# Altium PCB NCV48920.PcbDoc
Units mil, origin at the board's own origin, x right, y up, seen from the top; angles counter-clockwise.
Board outline 1000 x 1000 mil, 4 copper layers (Top Layer, GND_int, PWR_int, Bottom Layer), stack 61.654 mil thick; 6 components, 8 nets, 61 pads, 244 vias.
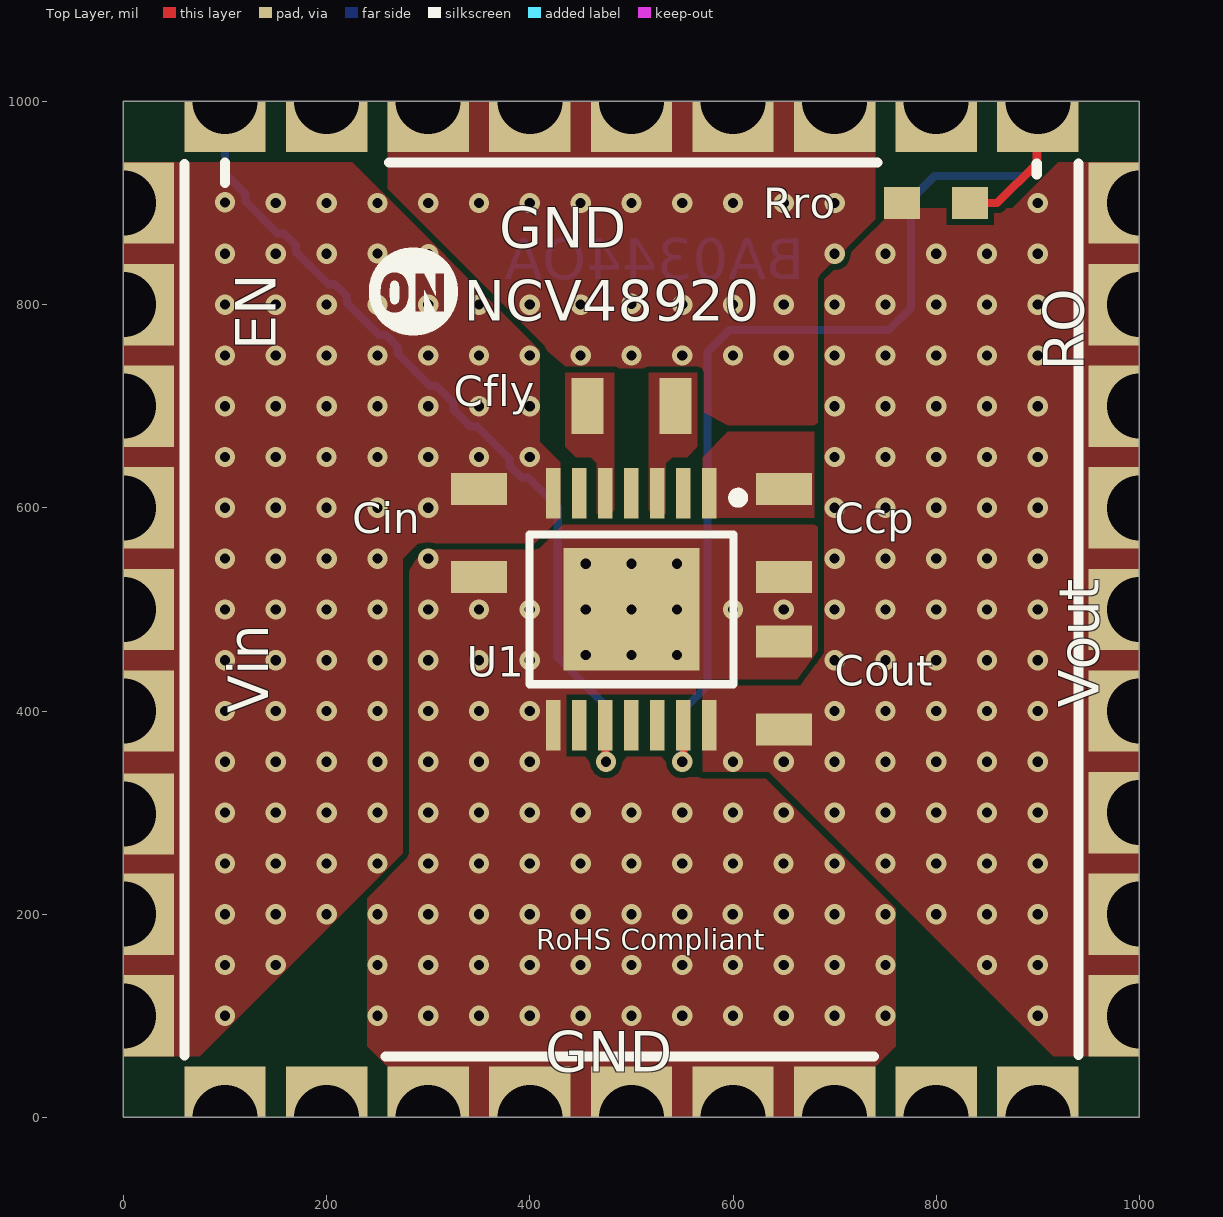
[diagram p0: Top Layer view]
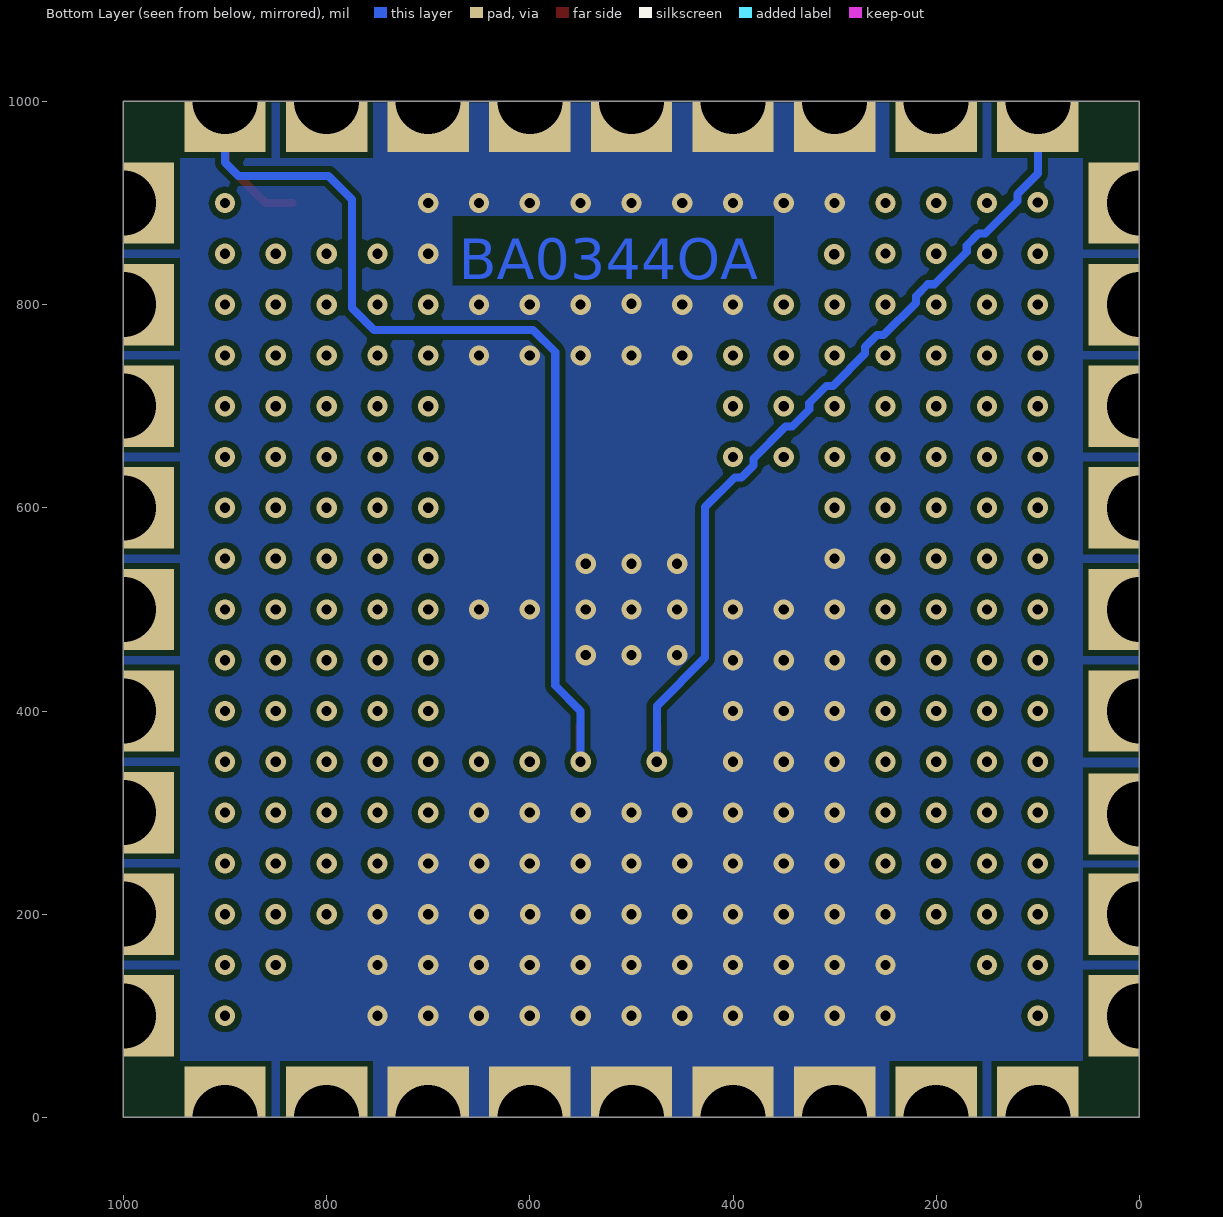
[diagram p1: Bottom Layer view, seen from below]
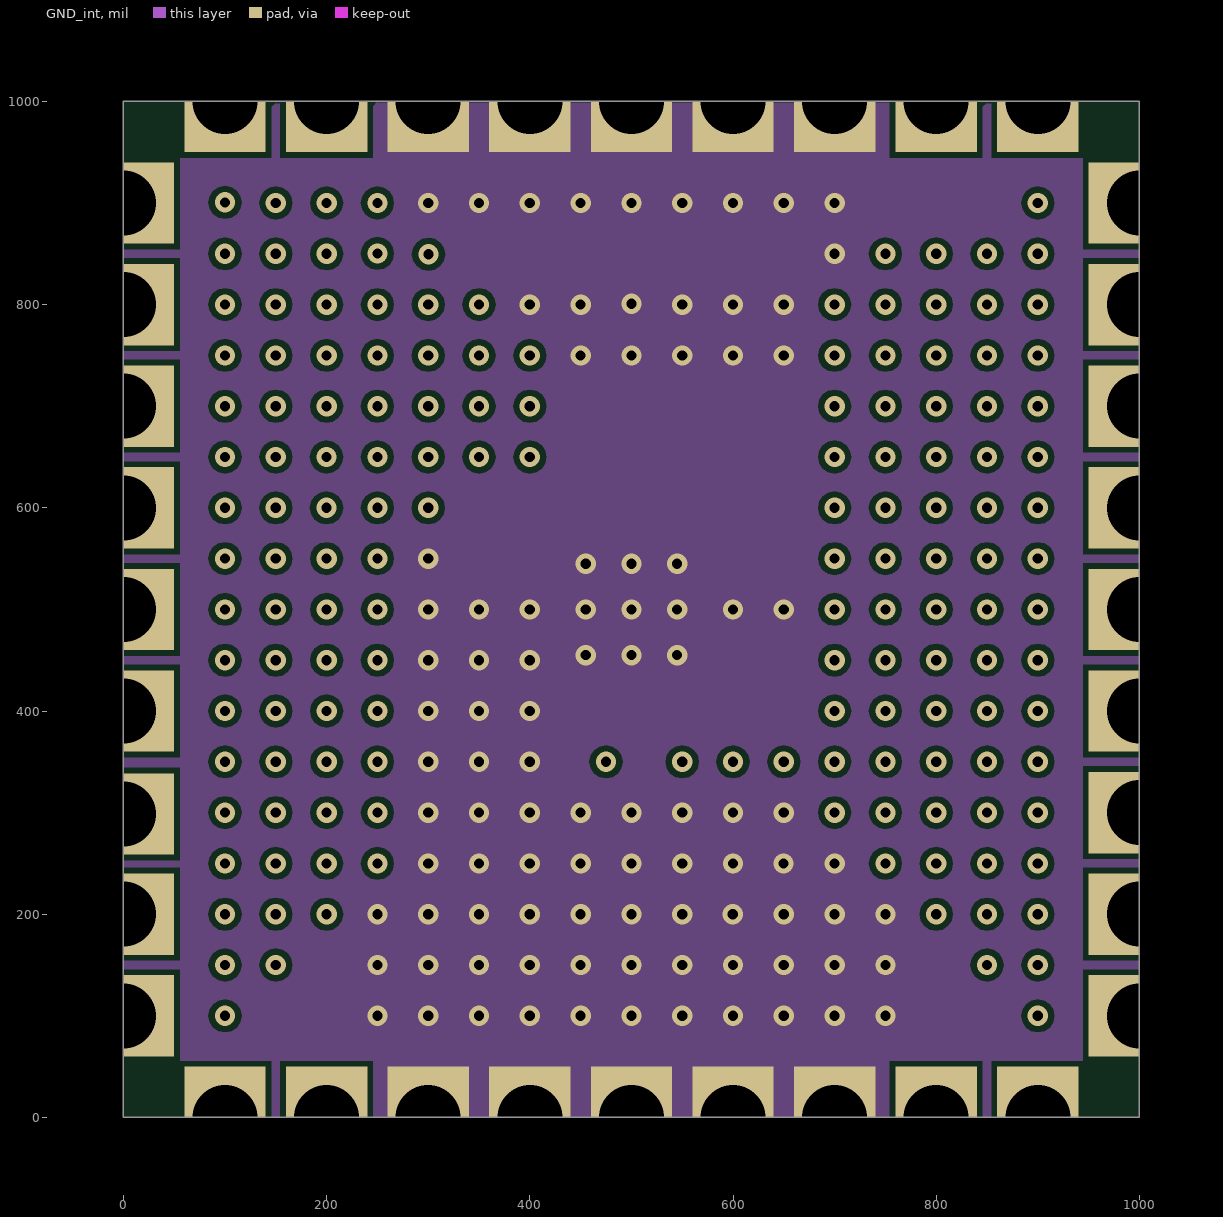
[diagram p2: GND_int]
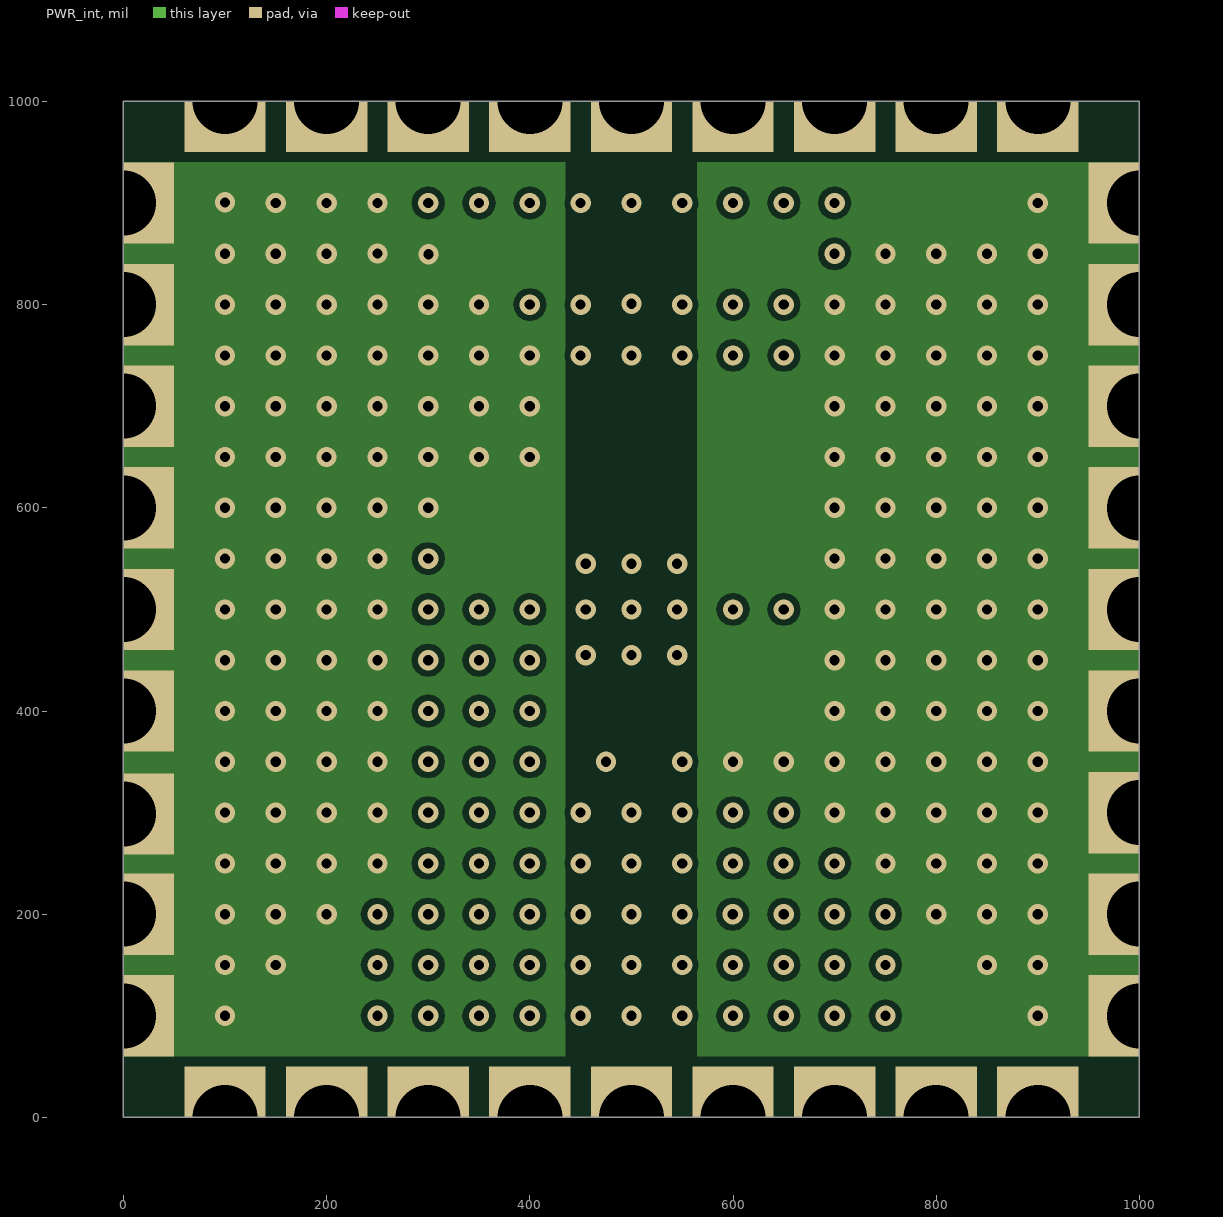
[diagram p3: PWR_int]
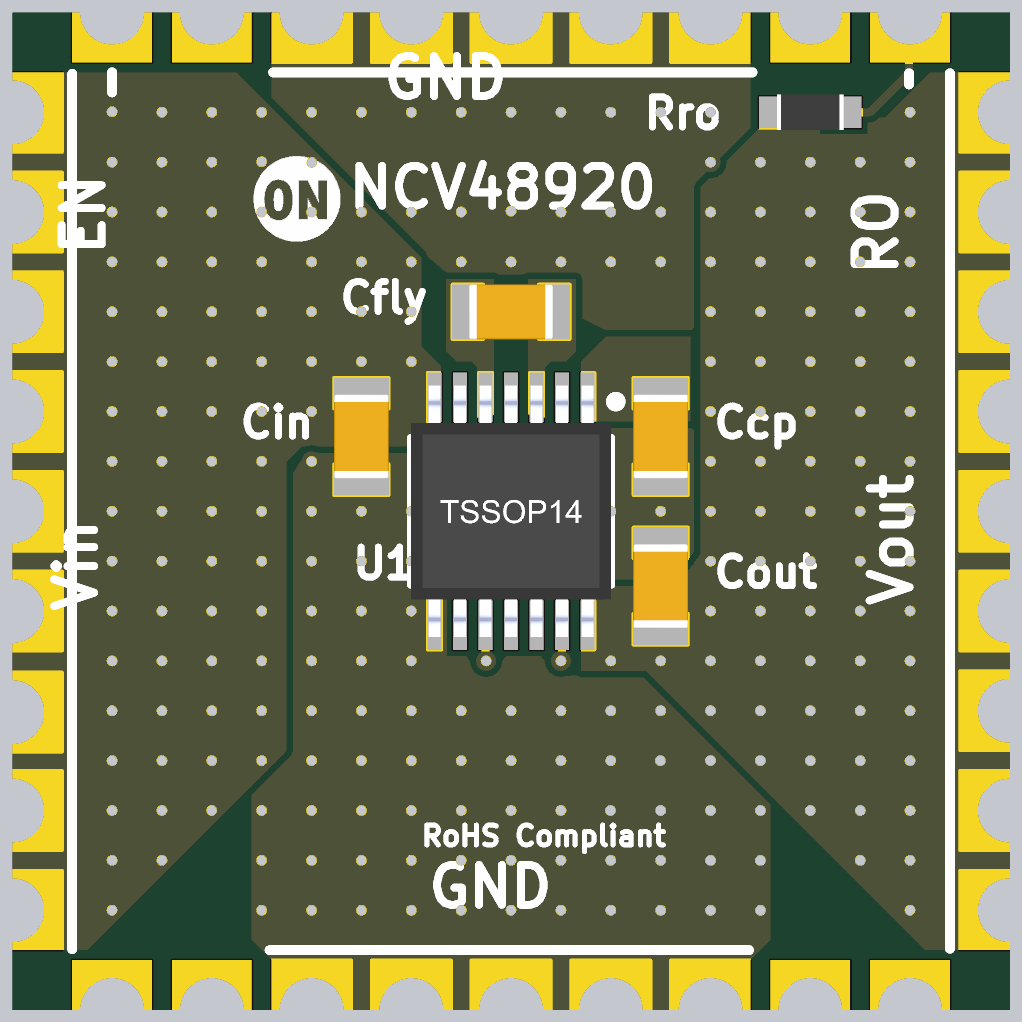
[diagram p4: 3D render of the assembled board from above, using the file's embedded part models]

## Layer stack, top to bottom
Top Solder: solder mask 0.4, Solder Resist, Dk 3.5
Top Layer: signal copper 0.7087
Dielectric 1: core 14.7638, FR-4, Dk 4.2
GND_int: signal copper 1.378
Dielectric 3: prepreg 27.9528, Dk 4.2
PWR_int: signal copper 1.378
Dielectric 2: core 14.7638, Dk 4.2
Bottom Layer: signal copper 0.7087
Bottom Solder: solder mask 0.4, Solder Resist, Dk 3.5

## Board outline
0,0 1000,0 1000,1000 0,1000
cut-out: -150,-400
cut-out: 0,-300

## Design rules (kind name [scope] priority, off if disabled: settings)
Clearance [All] p1: gap=6 ignorepadtopadclearanceinfootprint=FALSE except(0: Arc-Hole Track-Hole SMDPad-Hole THPad-Hole Via-Hole Fill-Hole Poly-Hole Region-Hole Text-Hole)
ComponentClearance [All] p1: gap=0 collisioncheckmode=3 verticalgap=0 showdistances=FALSE
DiffPairsRouting [All] p1: maxlimit=10 minlimit=6 mostfreqgap=10 toplayer_minwidth=6 toplayer_maxwidth=20 toplayer_prefwidth=10 midlayer1_minwidth=6 midlayer1_maxwidth=20 midlayer1_prefwidth=10 midlayer2_minwidth=6 midlayer2_maxwidth=20 midlayer2_prefwidth=10 bottomlayer_minwidth=6 bottomlayer_maxwidth=20 bottomlayer_prefwidth=10 maxuncoupledlength=500
Height [All] p1: minheight=0 maxheight=3000 prefheight=500
HoleSize [All] p1: absolutevalues=TRUE maxlimit=400 minlimit=8 maxpercent=80.000 minpercent=20.000
MinimumSolderMaskSliver [All] p1: minsoldermaskwidth=1.57
PlaneClearance [All] p1: clearance=6
PolygonConnect Polygon_Direct [All] p1: connectstyle=Direct reliefconductorwidth=10 reliefentries=4 polygonreliefangle="90 Angle" airgapwidth=10
PolygonConnect PolygonConnect_85 [All vs IsNamedPolygon('GND_L01_P2321')] p2: connectstyle=Direct reliefconductorwidth=10 reliefentries=4 polygonreliefangle="90 Angle" airgapwidth=10
PolygonConnect PolygonConnect_84 [All vs IsNamedPolygon('GND_L03_P1821')] p3: connectstyle=Direct reliefconductorwidth=10 reliefentries=4 polygonreliefangle="90 Angle" airgapwidth=10
PolygonConnect PolygonConnect_83 [All vs IsNamedPolygon('VOUTMP_L05_P1813')] p4: connectstyle=Direct reliefconductorwidth=10 reliefentries=4 polygonreliefangle="90 Angle" airgapwidth=10
PolygonConnect PolygonConnect_82 [All vs IsNamedPolygon('VOUTMP_L04_P1815')] p5: connectstyle=Direct reliefconductorwidth=10 reliefentries=4 polygonreliefangle="90 Angle" airgapwidth=10
PolygonConnect PolygonConnect_81 [All vs IsNamedPolygon('GND_L06_P2169')] p6: connectstyle=Direct reliefconductorwidth=10 reliefentries=4 polygonreliefangle="90 Angle" airgapwidth=10
PolygonConnect PolygonConnect_80 [All vs IsNamedPolygon('GND_L06_P2377')] p7: connectstyle=Direct reliefconductorwidth=10 reliefentries=4 polygonreliefangle="90 Angle" airgapwidth=10
PolygonConnect PolygonConnect_79 [All vs IsNamedPolygon('VOUTMP_L04_P1803')] p8: connectstyle=Direct reliefconductorwidth=10 reliefentries=4 polygonreliefangle="90 Angle" airgapwidth=10
PolygonConnect PolygonConnect_78 [All vs IsNamedPolygon('VCC_DUT_L04_P1801')] p9: connectstyle=Direct reliefconductorwidth=10 reliefentries=4 polygonreliefangle="90 Angle" airgapwidth=10
PolygonConnect PolygonConnect_77 [All vs IsNamedPolygon('GND_L06_P1795')] p10: thpad.connectstyle=Relief thpad.reliefconductorwidth=10 thpad.reliefentries=4 thpad.polygonreliefangle="90 Angle" thpad.airgapwidth=10 smdpad.connectstyle=Direct smdpad.reliefconductorwidth=10 smdpad.reliefentries=4 smdpad.polygonreliefangle="90 Angle" smdpad.airgapwidth=10 via.connectstyle=Direct via.reliefconductorwidth=10 via.reliefentries=4 via.polygonreliefangle="90 Angle" via.airgapwidth=10
PolygonConnect PolygonConnect_76 [All vs IsNamedPolygon('GND_L02_P1793')] p11: connectstyle=Direct reliefconductorwidth=10 reliefentries=4 polygonreliefangle="90 Angle" airgapwidth=10
PolygonConnect PolygonConnect_75 [All vs IsNamedPolygon('GND_L03_P1791')] p12: thpad.connectstyle=Relief thpad.reliefconductorwidth=10 thpad.reliefentries=4 thpad.polygonreliefangle="90 Angle" thpad.airgapwidth=10 smdpad.connectstyle=Direct smdpad.reliefconductorwidth=10 smdpad.reliefentries=4 smdpad.polygonreliefangle="90 Angle" smdpad.airgapwidth=10 via.connectstyle=Direct via.reliefconductorwidth=10 via.reliefentries=4 via.polygonreliefangle="90 Angle" via.airgapwidth=10
PolygonConnect PolygonConnect_74 [All vs IsNamedPolygon('NETQLMPB_5_L06_P1787')] p13: thpad.connectstyle=Relief thpad.reliefconductorwidth=10 thpad.reliefentries=4 thpad.polygonreliefangle="90 Angle" thpad.airgapwidth=10 smdpad.connectstyle=Direct smdpad.reliefconductorwidth=10 smdpad.reliefentries=4 smdpad.polygonreliefangle="90 Angle" smdpad.airgapwidth=10 via.connectstyle=Direct via.reliefconductorwidth=10 via.reliefentries=4 via.polygonreliefangle="90 Angle" via.airgapwidth=10
PolygonConnect PolygonConnect_73 [All vs IsNamedPolygon('NETQLMPA_5_L06_P1789')] p14: thpad.connectstyle=Relief thpad.reliefconductorwidth=10 thpad.reliefentries=4 thpad.polygonreliefangle="90 Angle" thpad.airgapwidth=10 smdpad.connectstyle=Direct smdpad.reliefconductorwidth=10 smdpad.reliefentries=4 smdpad.polygonreliefangle="90 Angle" smdpad.airgapwidth=10 via.connectstyle=Direct via.reliefconductorwidth=10 via.reliefentries=4 via.polygonreliefangle="90 Angle" via.airgapwidth=10
PolygonConnect PolygonConnect_72 [All vs IsNamedPolygon('NETQLMPC_5_L06_P1738')] p15: thpad.connectstyle=Relief thpad.reliefconductorwidth=10 thpad.reliefentries=4 thpad.polygonreliefangle="90 Angle" thpad.airgapwidth=10 smdpad.connectstyle=Direct smdpad.reliefconductorwidth=10 smdpad.reliefentries=4 smdpad.polygonreliefangle="90 Angle" smdpad.airgapwidth=10 via.connectstyle=Direct via.reliefconductorwidth=10 via.reliefentries=4 via.polygonreliefangle="90 Angle" via.airgapwidth=10
PolygonConnect PolygonConnect_71 [All vs IsNamedPolygon('NETQL12_5_L06_P1740')] p16: thpad.connectstyle=Relief thpad.reliefconductorwidth=10 thpad.reliefentries=4 thpad.polygonreliefangle="90 Angle" thpad.airgapwidth=10 smdpad.connectstyle=Direct smdpad.reliefconductorwidth=10 smdpad.reliefentries=4 smdpad.polygonreliefangle="90 Angle" smdpad.airgapwidth=10 via.connectstyle=Direct via.reliefconductorwidth=10 via.reliefentries=4 via.polygonreliefangle="90 Angle" via.airgapwidth=10
PolygonConnect PolygonConnect_70 [All vs IsNamedPolygon('NETQL12_5_L06_P1740')] p17: thpad.connectstyle=Relief thpad.reliefconductorwidth=10 thpad.reliefentries=4 thpad.polygonreliefangle="90 Angle" thpad.airgapwidth=10 smdpad.connectstyle=Direct smdpad.reliefconductorwidth=10 smdpad.reliefentries=4 smdpad.polygonreliefangle="90 Angle" smdpad.airgapwidth=10 via.connectstyle=Direct via.reliefconductorwidth=10 via.reliefentries=4 via.polygonreliefangle="90 Angle" via.airgapwidth=10
PolygonConnect PolygonConnect_69 [All vs IsNamedPolygon('NETQLMPD_5_L06_P1736')] p18: thpad.connectstyle=Relief thpad.reliefconductorwidth=10 thpad.reliefentries=4 thpad.polygonreliefangle="90 Angle" thpad.airgapwidth=10 smdpad.connectstyle=Direct smdpad.reliefconductorwidth=10 smdpad.reliefentries=4 smdpad.polygonreliefangle="90 Angle" smdpad.airgapwidth=10 via.connectstyle=Direct via.reliefconductorwidth=10 via.reliefentries=4 via.polygonreliefangle="90 Angle" via.airgapwidth=10
PolygonConnect PolygonConnect_68 [All vs IsNamedPolygon('NETQLMPA_5_L06_P1722')] p19: thpad.connectstyle=Relief thpad.reliefconductorwidth=10 thpad.reliefentries=4 thpad.polygonreliefangle="90 Angle" thpad.airgapwidth=10 smdpad.connectstyle=Direct smdpad.reliefconductorwidth=10 smdpad.reliefentries=4 smdpad.polygonreliefangle="90 Angle" smdpad.airgapwidth=10 via.connectstyle=Direct via.reliefconductorwidth=10 via.reliefentries=4 via.polygonreliefangle="90 Angle" via.airgapwidth=10
PolygonConnect PolygonConnect_67 [All vs IsNamedPolygon('GND_L03_P1716')] p20: connectstyle=Direct reliefconductorwidth=10 reliefentries=4 polygonreliefangle="90 Angle" airgapwidth=10
PolygonConnect PolygonConnect_66 [All vs IsNamedPolygon('GND_L03_P1716')] p21: thpad.connectstyle=Relief thpad.reliefconductorwidth=10 thpad.reliefentries=4 thpad.polygonreliefangle="90 Angle" thpad.airgapwidth=10 smdpad.connectstyle=Relief smdpad.reliefconductorwidth=10 smdpad.reliefentries=4 smdpad.polygonreliefangle="90 Angle" smdpad.airgapwidth=10 via.connectstyle=Direct via.reliefconductorwidth=10 via.reliefentries=4 via.polygonreliefangle="90 Angle" via.airgapwidth=10
PolygonConnect PolygonConnect_65 [All vs IsNamedPolygon('GND_L03_P1716')] p22: thpad.connectstyle=Direct thpad.reliefconductorwidth=10 thpad.reliefentries=4 thpad.polygonreliefangle="90 Angle" thpad.airgapwidth=10 smdpad.connectstyle=Relief smdpad.reliefconductorwidth=10 smdpad.reliefentries=4 smdpad.polygonreliefangle="90 Angle" smdpad.airgapwidth=10 via.connectstyle=Relief via.reliefconductorwidth=10 via.reliefentries=4 via.polygonreliefangle="90 Angle" via.airgapwidth=10
PolygonConnect PolygonConnect_64 [All vs IsNamedPolygon('GND_L03_P1716')] p23: connectstyle=Relief reliefconductorwidth=10 reliefentries=4 polygonreliefangle="90 Angle" airgapwidth=10
PolygonConnect PolygonConnect_63 [All vs IsNamedPolygon('GND_L04_P1728')] p24: connectstyle=Direct reliefconductorwidth=10 reliefentries=4 polygonreliefangle="90 Angle" airgapwidth=10
PolygonConnect PolygonConnect_62 [All vs IsNamedPolygon('G11_L04_P1730')] p25: thpad.connectstyle=Relief thpad.reliefconductorwidth=10 thpad.reliefentries=4 thpad.polygonreliefangle="90 Angle" thpad.airgapwidth=10 smdpad.connectstyle=Direct smdpad.reliefconductorwidth=10 smdpad.reliefentries=4 smdpad.polygonreliefangle="90 Angle" smdpad.airgapwidth=10 via.connectstyle=Direct via.reliefconductorwidth=10 via.reliefentries=4 via.polygonreliefangle="90 Angle" via.airgapwidth=10
PolygonConnect PolygonConnect_61 [All vs IsNamedPolygon('NETQL11_5_L04_P1732')] p26: thpad.connectstyle=Relief thpad.reliefconductorwidth=10 thpad.reliefentries=4 thpad.polygonreliefangle="90 Angle" thpad.airgapwidth=10 smdpad.connectstyle=Direct smdpad.reliefconductorwidth=10 smdpad.reliefentries=4 smdpad.polygonreliefangle="90 Angle" smdpad.airgapwidth=10 via.connectstyle=Direct via.reliefconductorwidth=10 via.reliefentries=4 via.polygonreliefangle="90 Angle" via.airgapwidth=10
PolygonConnect PolygonConnect_60 [All vs IsNamedPolygon('GND_L04_P1718')] p27: connectstyle=Direct reliefconductorwidth=10 reliefentries=4 polygonreliefangle="90 Angle" airgapwidth=10
PolygonConnect PolygonConnect_59 [All vs IsNamedPolygon('G12_L04_P1716')] p28: thpad.connectstyle=Relief thpad.reliefconductorwidth=10 thpad.reliefentries=4 thpad.polygonreliefangle="90 Angle" thpad.airgapwidth=10 smdpad.connectstyle=Direct smdpad.reliefconductorwidth=10 smdpad.reliefentries=4 smdpad.polygonreliefangle="90 Angle" smdpad.airgapwidth=10 via.connectstyle=Direct via.reliefconductorwidth=10 via.reliefentries=4 via.polygonreliefangle="90 Angle" via.airgapwidth=10
PolygonConnect PolygonConnect_58 [All vs IsNamedPolygon('NETQL12_5_L04_P1712')] p29: connectstyle=Direct reliefconductorwidth=10 reliefentries=4 polygonreliefangle="90 Angle" airgapwidth=10
PolygonConnect PolygonConnect_57 [All vs IsNamedPolygon('VOUT111_L01_P1710')] p30: thpad.connectstyle=Direct thpad.reliefconductorwidth=10 thpad.reliefentries=4 thpad.polygonreliefangle="90 Angle" thpad.airgapwidth=10 smdpad.connectstyle=Relief smdpad.reliefconductorwidth=10 smdpad.reliefentries=4 smdpad.polygonreliefangle="90 Angle" smdpad.airgapwidth=10 via.connectstyle=Direct via.reliefconductorwidth=10 via.reliefentries=4 via.polygonreliefangle="90 Angle" via.airgapwidth=10
PolygonConnect PolygonConnect_56 [All vs IsNamedPolygon('VCC_DUT_L06_P1734')] p31: connectstyle=Direct reliefconductorwidth=10 reliefentries=4 polygonreliefangle="90 Angle" airgapwidth=10
PolygonConnect PolygonConnect_55 [All vs IsNamedPolygon('NETC5_1_L01_P1688')] p32: thpad.connectstyle=Relief thpad.reliefconductorwidth=10 thpad.reliefentries=4 thpad.polygonreliefangle="90 Angle" thpad.airgapwidth=10 smdpad.connectstyle=Direct smdpad.reliefconductorwidth=10 smdpad.reliefentries=4 smdpad.polygonreliefangle="90 Angle" smdpad.airgapwidth=10 via.connectstyle=Direct via.reliefconductorwidth=10 via.reliefentries=4 via.polygonreliefangle="90 Angle" via.airgapwidth=10
PolygonConnect PolygonConnect_54 [All vs IsNamedPolygon('GND_L01_P1700')] p33: thpad.connectstyle=Relief thpad.reliefconductorwidth=10 thpad.reliefentries=4 thpad.polygonreliefangle="90 Angle" thpad.airgapwidth=10 smdpad.connectstyle=Direct smdpad.reliefconductorwidth=10 smdpad.reliefentries=4 smdpad.polygonreliefangle="90 Angle" smdpad.airgapwidth=10 via.connectstyle=Direct via.reliefconductorwidth=10 via.reliefentries=4 via.polygonreliefangle="90 Angle" via.airgapwidth=10
PolygonConnect PolygonConnect_53 [All vs IsNamedPolygon('GND_L01_P1608')] p34: thpad.connectstyle=Relief thpad.reliefconductorwidth=10 thpad.reliefentries=4 thpad.polygonreliefangle="90 Angle" thpad.airgapwidth=10 smdpad.connectstyle=Direct smdpad.reliefconductorwidth=10 smdpad.reliefentries=4 smdpad.polygonreliefangle="90 Angle" smdpad.airgapwidth=10 via.connectstyle=Direct via.reliefconductorwidth=10 via.reliefentries=4 via.polygonreliefangle="90 Angle" via.airgapwidth=10
PolygonConnect PolygonConnect_52 [All vs IsNamedPolygon('VREF_L01_P1696')] p35: connectstyle=Direct reliefconductorwidth=10 reliefentries=4 polygonreliefangle="90 Angle" airgapwidth=10
PolygonConnect PolygonConnect_51 [All vs IsNamedPolygon('VREF_L01_P1696')] p36: thpad.connectstyle=Relief thpad.reliefconductorwidth=10 thpad.reliefentries=4 thpad.polygonreliefangle="90 Angle" thpad.airgapwidth=10 smdpad.connectstyle=Direct smdpad.reliefconductorwidth=10 smdpad.reliefentries=4 smdpad.polygonreliefangle="90 Angle" smdpad.airgapwidth=10 via.connectstyle=Direct via.reliefconductorwidth=10 via.reliefentries=4 via.polygonreliefangle="90 Angle" via.airgapwidth=10
PolygonConnect PolygonConnect_50 [All vs IsNamedPolygon('NETC2_1_L01_P1698')] p37: thpad.connectstyle=Relief thpad.reliefconductorwidth=10 thpad.reliefentries=4 thpad.polygonreliefangle="90 Angle" thpad.airgapwidth=10 smdpad.connectstyle=Direct smdpad.reliefconductorwidth=10 smdpad.reliefentries=4 smdpad.polygonreliefangle="90 Angle" smdpad.airgapwidth=10 via.connectstyle=Direct via.reliefconductorwidth=10 via.reliefentries=4 via.polygonreliefangle="90 Angle" via.airgapwidth=10
PolygonConnect PolygonConnect_49 [All vs IsNamedPolygon('NETC1_1_L01_P1694')] p38: thpad.connectstyle=Relief thpad.reliefconductorwidth=10 thpad.reliefentries=4 thpad.polygonreliefangle="90 Angle" thpad.airgapwidth=10 smdpad.connectstyle=Direct smdpad.reliefconductorwidth=10 smdpad.reliefentries=4 smdpad.polygonreliefangle="90 Angle" smdpad.airgapwidth=10 via.connectstyle=Direct via.reliefconductorwidth=10 via.reliefentries=4 via.polygonreliefangle="90 Angle" via.airgapwidth=10
PolygonConnect PolygonConnect_48 [All vs IsNamedPolygon('VID_BUFF_L01_P1690')] p39: thpad.connectstyle=Relief thpad.reliefconductorwidth=10 thpad.reliefentries=4 thpad.polygonreliefangle="90 Angle" thpad.airgapwidth=10 smdpad.connectstyle=Direct smdpad.reliefconductorwidth=10 smdpad.reliefentries=4 smdpad.polygonreliefangle="90 Angle" smdpad.airgapwidth=10 via.connectstyle=Direct via.reliefconductorwidth=10 via.reliefentries=4 via.polygonreliefangle="90 Angle" via.airgapwidth=10
PolygonConnect PolygonConnect_47 [All vs IsNamedPolygon('NETCVCC_1_L01_P1690')] p40: thpad.connectstyle=Relief thpad.reliefconductorwidth=10 thpad.reliefentries=4 thpad.polygonreliefangle="90 Angle" thpad.airgapwidth=10 smdpad.connectstyle=Direct smdpad.reliefconductorwidth=10 smdpad.reliefentries=4 smdpad.polygonreliefangle="90 Angle" smdpad.airgapwidth=10 via.connectstyle=Direct via.reliefconductorwidth=10 via.reliefentries=4 via.polygonreliefangle="90 Angle" via.airgapwidth=10
PolygonConnect PolygonConnect_46 [All vs IsNamedPolygon('REFIN_L01_P1686')] p41: thpad.connectstyle=Relief thpad.reliefconductorwidth=10 thpad.reliefentries=4 thpad.polygonreliefangle="90 Angle" thpad.airgapwidth=10 smdpad.connectstyle=Direct smdpad.reliefconductorwidth=10 smdpad.reliefentries=4 smdpad.polygonreliefangle="90 Angle" smdpad.airgapwidth=10 via.connectstyle=Direct via.reliefconductorwidth=10 via.reliefentries=4 via.polygonreliefangle="90 Angle" via.airgapwidth=10
PolygonConnect PolygonConnect_45 [All vs IsNamedPolygon('CSREF_L06_P1706')] p42: thpad.connectstyle=Relief thpad.reliefconductorwidth=10 thpad.reliefentries=4 thpad.polygonreliefangle="90 Angle" thpad.airgapwidth=10 smdpad.connectstyle=Direct smdpad.reliefconductorwidth=10 smdpad.reliefentries=4 smdpad.polygonreliefangle="90 Angle" smdpad.airgapwidth=10 via.connectstyle=Direct via.reliefconductorwidth=10 via.reliefentries=4 via.polygonreliefangle="90 Angle" via.airgapwidth=10
PolygonConnect PolygonConnect_44 [All vs IsNamedPolygon('GND_L01_P1612')] p43: thpad.connectstyle=Relief thpad.reliefconductorwidth=10 thpad.reliefentries=4 thpad.polygonreliefangle="90 Angle" thpad.airgapwidth=10 smdpad.connectstyle=Direct smdpad.reliefconductorwidth=10 smdpad.reliefentries=4 smdpad.polygonreliefangle="90 Angle" smdpad.airgapwidth=10 via.connectstyle=Direct via.reliefconductorwidth=10 via.reliefentries=4 via.polygonreliefangle="90 Angle" via.airgapwidth=10
PolygonConnect PolygonConnect_43 [All vs IsNamedPolygon('CSREF_L01_P1682')] p44: thpad.connectstyle=Relief thpad.reliefconductorwidth=10 thpad.reliefentries=4 thpad.polygonreliefangle="90 Angle" thpad.airgapwidth=10 smdpad.connectstyle=Direct smdpad.reliefconductorwidth=10 smdpad.reliefentries=4 smdpad.polygonreliefangle="90 Angle" smdpad.airgapwidth=10 via.connectstyle=Direct via.reliefconductorwidth=10 via.reliefentries=4 via.polygonreliefangle="90 Angle" via.airgapwidth=10
PolygonConnect PolygonConnect_42 [All vs IsNamedPolygon('VIN1_L06_P222')] p45: thpad.connectstyle=Relief thpad.reliefconductorwidth=10 thpad.reliefentries=4 thpad.polygonreliefangle="90 Angle" thpad.airgapwidth=10 smdpad.connectstyle=Direct smdpad.reliefconductorwidth=10 smdpad.reliefentries=4 smdpad.polygonreliefangle="90 Angle" smdpad.airgapwidth=10 via.connectstyle=Direct via.reliefconductorwidth=10 via.reliefentries=4 via.polygonreliefangle="90 Angle" via.airgapwidth=10
PolygonConnect PolygonConnect_41 [All vs IsNamedPolygon('VIN1_L06_P1450')] p46: thpad.connectstyle=Relief thpad.reliefconductorwidth=10 thpad.reliefentries=4 thpad.polygonreliefangle="90 Angle" thpad.airgapwidth=10 smdpad.connectstyle=Direct smdpad.reliefconductorwidth=10 smdpad.reliefentries=4 smdpad.polygonreliefangle="90 Angle" smdpad.airgapwidth=10 via.connectstyle=Direct via.reliefconductorwidth=10 via.reliefentries=4 via.polygonreliefangle="90 Angle" via.airgapwidth=10
PolygonConnect PolygonConnect_40 [All vs IsNamedPolygon('VIN1_L06_P1450')] p47: thpad.connectstyle=Relief thpad.reliefconductorwidth=10 thpad.reliefentries=4 thpad.polygonreliefangle="90 Angle" thpad.airgapwidth=10 smdpad.connectstyle=Direct smdpad.reliefconductorwidth=10 smdpad.reliefentries=4 smdpad.polygonreliefangle="90 Angle" smdpad.airgapwidth=10 via.connectstyle=Direct via.reliefconductorwidth=10 via.reliefentries=4 via.polygonreliefangle="90 Angle" via.airgapwidth=10
PolygonConnect PolygonConnect_39 [All vs IsNamedPolygon('VIN1_L06_P1530')] p48: thpad.connectstyle=Relief thpad.reliefconductorwidth=10 thpad.reliefentries=4 thpad.polygonreliefangle="90 Angle" thpad.airgapwidth=10 smdpad.connectstyle=Direct smdpad.reliefconductorwidth=10 smdpad.reliefentries=4 smdpad.polygonreliefangle="90 Angle" smdpad.airgapwidth=10 via.connectstyle=Direct via.reliefconductorwidth=10 via.reliefentries=4 via.polygonreliefangle="90 Angle" via.airgapwidth=10
PolygonConnect PolygonConnect_38 [All vs IsNamedPolygon('VIN1_L06_P1562')] p49: thpad.connectstyle=Relief thpad.reliefconductorwidth=10 thpad.reliefentries=4 thpad.polygonreliefangle="90 Angle" thpad.airgapwidth=10 smdpad.connectstyle=Direct smdpad.reliefconductorwidth=10 smdpad.reliefentries=4 smdpad.polygonreliefangle="90 Angle" smdpad.airgapwidth=10 via.connectstyle=Direct via.reliefconductorwidth=10 via.reliefentries=4 via.polygonreliefangle="90 Angle" via.airgapwidth=10
PolygonConnect PolygonConnect_37 [All vs IsNamedPolygon('VIN1_L06_P1530')] p50: thpad.connectstyle=Relief thpad.reliefconductorwidth=10 thpad.reliefentries=4 thpad.polygonreliefangle="90 Angle" thpad.airgapwidth=10 smdpad.connectstyle=Direct smdpad.reliefconductorwidth=10 smdpad.reliefentries=4 smdpad.polygonreliefangle="90 Angle" smdpad.airgapwidth=10 via.connectstyle=Direct via.reliefconductorwidth=10 via.reliefentries=4 via.polygonreliefangle="90 Angle" via.airgapwidth=10
PolygonConnect PolygonConnect_36 [All vs IsNamedPolygon('VIN1_L06_P1530')] p51: thpad.connectstyle=Relief thpad.reliefconductorwidth=10 thpad.reliefentries=4 thpad.polygonreliefangle="90 Angle" thpad.airgapwidth=10 smdpad.connectstyle=Direct smdpad.reliefconductorwidth=10 smdpad.reliefentries=4 smdpad.polygonreliefangle="90 Angle" smdpad.airgapwidth=10 via.connectstyle=Direct via.reliefconductorwidth=10 via.reliefentries=4 via.polygonreliefangle="90 Angle" via.airgapwidth=10
PolygonConnect PolygonConnect_35 [All vs IsNamedPolygon('VIN1_L06_P1636')] p52: thpad.connectstyle=Relief thpad.reliefconductorwidth=10 thpad.reliefentries=4 thpad.polygonreliefangle="90 Angle" thpad.airgapwidth=10 smdpad.connectstyle=Direct smdpad.reliefconductorwidth=10 smdpad.reliefentries=4 smdpad.polygonreliefangle="90 Angle" smdpad.airgapwidth=10 via.connectstyle=Direct via.reliefconductorwidth=10 via.reliefentries=4 via.polygonreliefangle="90 Angle" via.airgapwidth=10
PolygonConnect PolygonConnect_34 [All vs IsNamedPolygon('GND_L01_P1614')] p53: thpad.connectstyle=Relief thpad.reliefconductorwidth=10 thpad.reliefentries=4 thpad.polygonreliefangle="90 Angle" thpad.airgapwidth=10 smdpad.connectstyle=Direct smdpad.reliefconductorwidth=10 smdpad.reliefentries=4 smdpad.polygonreliefangle="90 Angle" smdpad.airgapwidth=10 via.connectstyle=Direct via.reliefconductorwidth=10 via.reliefentries=4 via.polygonreliefangle="90 Angle" via.airgapwidth=10
PolygonConnect PolygonConnect_33 [All vs IsNamedPolygon('CSSUM_L01_P1600')] p54: thpad.connectstyle=Relief thpad.reliefconductorwidth=10 thpad.reliefentries=4 thpad.polygonreliefangle="90 Angle" thpad.airgapwidth=10 smdpad.connectstyle=Direct smdpad.reliefconductorwidth=10 smdpad.reliefentries=4 smdpad.polygonreliefangle="90 Angle" smdpad.airgapwidth=10 via.connectstyle=Direct via.reliefconductorwidth=10 via.reliefentries=4 via.polygonreliefangle="90 Angle" via.airgapwidth=10
PolygonConnect PolygonConnect_32 [All vs IsNamedPolygon('NETC2_1_L01_P1604')] p55: thpad.connectstyle=Relief thpad.reliefconductorwidth=10 thpad.reliefentries=4 thpad.polygonreliefangle="90 Angle" thpad.airgapwidth=10 smdpad.connectstyle=Direct smdpad.reliefconductorwidth=10 smdpad.reliefentries=4 smdpad.polygonreliefangle="90 Angle" smdpad.airgapwidth=10 via.connectstyle=Direct via.reliefconductorwidth=10 via.reliefentries=4 via.polygonreliefangle="90 Angle" via.airgapwidth=10
PolygonConnect PolygonConnect_31 [All vs IsNamedPolygon('GND_L01_P1608')] p56: thpad.connectstyle=Relief thpad.reliefconductorwidth=10 thpad.reliefentries=4 thpad.polygonreliefangle="90 Angle" thpad.airgapwidth=10 smdpad.connectstyle=Direct smdpad.reliefconductorwidth=10 smdpad.reliefentries=4 smdpad.polygonreliefangle="90 Angle" smdpad.airgapwidth=10 via.connectstyle=Direct via.reliefconductorwidth=10 via.reliefentries=4 via.polygonreliefangle="90 Angle" via.airgapwidth=10
PolygonConnect PolygonConnect_30 [All vs IsNamedPolygon('VCC_DUT_L01_P1606')] p57: thpad.connectstyle=Relief thpad.reliefconductorwidth=10 thpad.reliefentries=4 thpad.polygonreliefangle="90 Angle" thpad.airgapwidth=10 smdpad.connectstyle=Direct smdpad.reliefconductorwidth=10 smdpad.reliefentries=4 smdpad.polygonreliefangle="90 Angle" smdpad.airgapwidth=10 via.connectstyle=Direct via.reliefconductorwidth=10 via.reliefentries=4 via.polygonreliefangle="90 Angle" via.airgapwidth=10
PolygonConnect PolygonConnect_29 [All vs IsNamedPolygon('GND_L01_P1614')] p58: thpad.connectstyle=Relief thpad.reliefconductorwidth=10 thpad.reliefentries=4 thpad.polygonreliefangle="90 Angle" thpad.airgapwidth=10 smdpad.connectstyle=Relief smdpad.reliefconductorwidth=10 smdpad.reliefentries=4 smdpad.polygonreliefangle="90 Angle" smdpad.airgapwidth=10 via.connectstyle=Direct via.reliefconductorwidth=10 via.reliefentries=4 via.polygonreliefangle="90 Angle" via.airgapwidth=10
PolygonConnect PolygonConnect_28 [All vs IsNamedPolygon('GND_L01_P2387')] p59: thpad.connectstyle=Relief thpad.reliefconductorwidth=10 thpad.reliefentries=4 thpad.polygonreliefangle="90 Angle" thpad.airgapwidth=10 smdpad.connectstyle=Direct smdpad.reliefconductorwidth=10 smdpad.reliefentries=4 smdpad.polygonreliefangle="90 Angle" smdpad.airgapwidth=10 via.connectstyle=Direct via.reliefconductorwidth=10 via.reliefentries=4 via.polygonreliefangle="90 Angle" via.airgapwidth=10
PolygonConnect PolygonConnect_27 [All vs IsNamedPolygon('GND_L01_P2387')] p60: thpad.connectstyle=Relief thpad.reliefconductorwidth=10 thpad.reliefentries=4 thpad.polygonreliefangle="90 Angle" thpad.airgapwidth=10 smdpad.connectstyle=Relief smdpad.reliefconductorwidth=10 smdpad.reliefentries=4 smdpad.polygonreliefangle="90 Angle" smdpad.airgapwidth=10 via.connectstyle=Direct via.reliefconductorwidth=10 via.reliefentries=4 via.polygonreliefangle="90 Angle" via.airgapwidth=10
PolygonConnect PolygonConnect_26 [All vs IsNamedPolygon('GND_L01_P2387')] p61: thpad.connectstyle=Relief thpad.reliefconductorwidth=10 thpad.reliefentries=4 thpad.polygonreliefangle="90 Angle" thpad.airgapwidth=10 smdpad.connectstyle=Direct smdpad.reliefconductorwidth=10 smdpad.reliefentries=4 smdpad.polygonreliefangle="90 Angle" smdpad.airgapwidth=10 via.connectstyle=Direct via.reliefconductorwidth=10 via.reliefentries=4 via.polygonreliefangle="90 Angle" via.airgapwidth=10
PolygonConnect PolygonConnect_25 [All vs IsNamedPolygon('SW0_L01_P466')] p62: thpad.connectstyle=Relief thpad.reliefconductorwidth=10 thpad.reliefentries=4 thpad.polygonreliefangle="90 Angle" thpad.airgapwidth=10 smdpad.connectstyle=Direct smdpad.reliefconductorwidth=10 smdpad.reliefentries=4 smdpad.polygonreliefangle="90 Angle" smdpad.airgapwidth=10 via.connectstyle=Direct via.reliefconductorwidth=10 via.reliefentries=4 via.polygonreliefangle="90 Angle" via.airgapwidth=10
PolygonConnect PolygonConnect_24 [All vs IsNamedPolygon('VIN1_L01_P1602')] p63: thpad.connectstyle=Relief thpad.reliefconductorwidth=10 thpad.reliefentries=4 thpad.polygonreliefangle="90 Angle" thpad.airgapwidth=10 smdpad.connectstyle=Direct smdpad.reliefconductorwidth=10 smdpad.reliefentries=4 smdpad.polygonreliefangle="90 Angle" smdpad.airgapwidth=10 via.connectstyle=Direct via.reliefconductorwidth=10 via.reliefentries=4 via.polygonreliefangle="90 Angle" via.airgapwidth=10
PolygonConnect PolygonConnect_23 [All vs IsNamedPolygon('CSSUM_L01_P1600')] p64: thpad.connectstyle=Direct thpad.reliefconductorwidth=10 thpad.reliefentries=4 thpad.polygonreliefangle="90 Angle" thpad.airgapwidth=10 smdpad.connectstyle=Relief smdpad.reliefconductorwidth=10 smdpad.reliefentries=4 smdpad.polygonreliefangle="90 Angle" smdpad.airgapwidth=10 via.connectstyle=Direct via.reliefconductorwidth=10 via.reliefentries=4 via.polygonreliefangle="90 Angle" via.airgapwidth=10
PolygonConnect PolygonConnect_22 [All vs IsNamedPolygon('CSSUM_L01_P1600')] p65: connectstyle=Relief reliefconductorwidth=10 reliefentries=4 polygonreliefangle="90 Angle" airgapwidth=10
PolygonConnect PolygonConnect_21 [All vs IsNamedPolygon('Top Layer-Vin1')] p66: connectstyle=Direct reliefconductorwidth=10 reliefentries=4 polygonreliefangle="90 Angle" airgapwidth=10
PolygonConnect PolygonConnect_20 [All vs IsNamedPolygon('Top Layer-Vin1')] p67: connectstyle=Direct reliefconductorwidth=10 reliefentries=4 polygonreliefangle="90 Angle" airgapwidth=10
PolygonConnect PolygonConnect_19 [All vs IsNamedPolygon('TOP-SW8')] p68: connectstyle=Direct reliefconductorwidth=10 reliefentries=4 polygonreliefangle="90 Angle" airgapwidth=10
PolygonConnect PolygonConnect_18 [All vs IsNamedPolygon('TOP-VOU8')] p69: connectstyle=Direct reliefconductorwidth=10 reliefentries=4 polygonreliefangle="90 Angle" airgapwidth=10
PolygonConnect PolygonConnect_17 [All vs IsNamedPolygon('Top Layer-Vin1')] p70: connectstyle=Direct reliefconductorwidth=10 reliefentries=4 polygonreliefangle="90 Angle" airgapwidth=10
PolygonConnect PolygonConnect_16 [All vs IsNamedPolygon('Top Layer-GND')] p71: connectstyle=Direct reliefconductorwidth=10 reliefentries=4 polygonreliefangle="90 Angle" airgapwidth=10
PolygonConnect PolygonConnect_15 [All vs IsNamedPolygon('Top Layer-GND')] p72: connectstyle=Direct reliefconductorwidth=10 reliefentries=4 polygonreliefangle="90 Angle" airgapwidth=10
PolygonConnect PolygonConnect_14 [All vs IsNamedPolygon('Top Layer-Vin1')] p73: connectstyle=Direct reliefconductorwidth=10 reliefentries=4 polygonreliefangle="90 Angle" airgapwidth=10
PolygonConnect PolygonConnect_13 [All vs IsNamedPolygon('TOP-VOU8')] p74: connectstyle=Direct reliefconductorwidth=10 reliefentries=4 polygonreliefangle="90 Angle" airgapwidth=10
PolygonConnect PolygonConnect_12 [All vs IsNamedPolygon('TOP-SW8')] p75: connectstyle=Direct reliefconductorwidth=10 reliefentries=4 polygonreliefangle="90 Angle" airgapwidth=10
PolygonConnect PolygonConnect_11 [All vs IsNamedPolygon('BOTTOM-GND')] p76: connectstyle=Direct reliefconductorwidth=10 reliefentries=4 polygonreliefangle="90 Angle" airgapwidth=10
PolygonConnect PolygonConnect_10 [All vs IsNamedPolygon('BOTTOM-GND 1')] p77: connectstyle=Direct reliefconductorwidth=10 reliefentries=4 polygonreliefangle="90 Angle" airgapwidth=10
PolygonConnect PolygonConnect_9 [All vs IsNamedPolygon('BOTTOM-N28887058')] p78: connectstyle=Direct reliefconductorwidth=10 reliefentries=4 polygonreliefangle="90 Angle" airgapwidth=10
PolygonConnect PolygonConnect_8 [All vs IsNamedPolygon('BOTTOM-N28887226')] p79: connectstyle=Direct reliefconductorwidth=10 reliefentries=4 polygonreliefangle="90 Angle" airgapwidth=10
PolygonConnect PolygonConnect_7 [All vs IsNamedPolygon('BOTTOM-AGND 16')] p80: connectstyle=Direct reliefconductorwidth=10 reliefentries=4 polygonreliefangle="90 Angle" airgapwidth=10
PolygonConnect PolygonConnect_6 [All vs IsNamedPolygon('VIN1_L06_P1534')] p81: connectstyle=Direct reliefconductorwidth=10 reliefentries=4 polygonreliefangle="90 Angle" airgapwidth=10
PolygonConnect PolygonConnect_5 [All vs IsNamedPolygon('BOTTOM-AGND 8')] p82: connectstyle=Direct reliefconductorwidth=10 reliefentries=4 polygonreliefangle="90 Angle" airgapwidth=10
PolygonConnect PolygonConnect_4 [All vs IsNamedPolygon('TOP-VOU8')] p83: connectstyle=Direct reliefconductorwidth=10 reliefentries=4 polygonreliefangle="90 Angle" airgapwidth=10
PolygonConnect PolygonConnect_3 [All vs IsNamedPolygon('TOP-SW8')] p84: connectstyle=Direct reliefconductorwidth=10 reliefentries=4 polygonreliefangle="90 Angle" airgapwidth=10
PolygonConnect PolygonConnect_2 [All vs IsNamedPolygon('TOP-N28860843')] p85: connectstyle=Direct reliefconductorwidth=10 reliefentries=4 polygonreliefangle="90 Angle" airgapwidth=10
PolygonConnect PolygonConnect_1 [All vs IsNamedPolygon('Top Layer-Vin1')] p86: connectstyle=Direct reliefconductorwidth=10 reliefentries=4 polygonreliefangle="90 Angle" airgapwidth=10
PolygonConnect [All vs IsNamedPolygon('Top Layer-GND')] p87: connectstyle=Direct reliefconductorwidth=10 reliefentries=4 polygonreliefangle="90 Angle" airgapwidth=10
PolygonConnect "Top Layer Polygons" [(InPolygon AND OnLayer('top Layer'))] p88: connectstyle=Direct reliefconductorwidth=10 reliefentries=4 polygonreliefangle="90 Angle" airgapwidth=10
PolygonConnect MOD_1x1_36 [All vs (OnLayer('Top Layer') AND HasFootprint('MOD_1x1_36'))] p89: thpad.connectstyle=Direct thpad.reliefconductorwidth=10 thpad.reliefentries=4 thpad.polygonreliefangle="90 Angle" thpad.airgapwidth=10 smdpad.connectstyle=Relief smdpad.reliefconductorwidth=10 smdpad.reliefentries=4 smdpad.polygonreliefangle="90 Angle" smdpad.airgapwidth=10 via.connectstyle=Direct via.reliefconductorwidth=10 via.reliefentries=4 via.polygonreliefangle="90 Angle" via.airgapwidth=10
PolygonConnect "Top Layer Vbat" [All vs IsNamedPolygon('Top Layer-Vbat')] p90: connectstyle=Direct reliefconductorwidth=10 reliefentries=4 polygonreliefangle="90 Angle" airgapwidth=10
PolygonConnect "Top Layer Vbat GND" [All vs IsNamedPolygon('GND_L03_P1716')] p91: connectstyle=Direct reliefconductorwidth=10 reliefentries=4 polygonreliefangle="90 Angle" airgapwidth=10
PolygonConnect "Top Layer Vbat RB" [All vs IsNamedPolygon('Top Layer-Vbat_RB')] p92: connectstyle=Direct reliefconductorwidth=10 reliefentries=4 polygonreliefangle="90 Angle" airgapwidth=10
RoomDefinition NCV48920 [InComponentClass('NCV48920')] p1: confinementstyle=ConfineIn formatcopy=TRUE lockcomponents=FALSE outline 0,-1.22 1000,-1.22 1000,1000 0,1000
RoutingCorners [All] p1: cornerstyle=45-Degree minsetback=50 maxsetback=50
RoutingVias [All] p1: holewidth=11.81 width=23.62 viastyle="Through Hole" minholewidth=8 minwidth=16 maxholewidth=200 maxwidth=400
SilkToSilkClearance [All] p1: silktosilkclearance=0
SilkToSolderMaskClearance SilkToSolderMaskClearance_text [Locked and IsText] p1: minsilkscreentomaskgap=0 clearancetoexposedcopper=TRUE
SilkToSolderMaskClearance [IsPad] p2: minsilkscreentomaskgap=0 clearancetoexposedcopper=TRUE
SolderMaskExpansion [All] p1: expansion=1.57
Width [All] p1: maxlimit=60 minlimit=6 preferedwidth=10 minimp=50.000000 maximp=50.000000 favimp=50.000000
21 further rules are at their usual default settings.

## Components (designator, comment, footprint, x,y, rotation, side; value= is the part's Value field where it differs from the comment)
Ccp "GCM21BR71A106KE22K" 0805_CAP_MAX 650,575 r270 top value=10u
Cfly "GCM21BR71A106KE22K" 0805_CAP_MAX 500,700 r180 top value=10u
Cin "GCM21BR71A106KE22K" 0805_CAP_MAX 350,575 r270 top value=1u
Cout "GCM21BR71A106KE22K" 0805_CAP_MAX 650,425 r90 top value=10u
Rro "RC0402FR-07100KL" 0603_RES 800,900 r0 top value=10k
U1 "NCV48920" TSSOP-14-EP 500,500 r270 top

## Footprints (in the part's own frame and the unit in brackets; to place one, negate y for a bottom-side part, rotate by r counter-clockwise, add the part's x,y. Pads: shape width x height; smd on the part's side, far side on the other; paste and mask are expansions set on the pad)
0603_RES [mm] "0603_Reflow, YAGEO"
  rect 0.9x0.8 smd: 1(-0.85,0) 2(0.85,0)
  body extent -0.85,-0.45 0.85,0.45, height 0.55
0805_CAP_MAX [mm] "0805, MLCC, GCM Series, max dimensions from reflow soldering"
  rect 0.8x1.4 smd: 1(-1.1,0) 2(1.1,0)
  body extent -1.07,-0.7 1.07,0.7, height 1.4
TSSOP-14-EP [mm] "SOP, 14-Leads Exposed PAD, Body 5.1x4.5mm, Pitch 0.65mm"
  rect 1.26x0.36 smd: 1(-2.9,1.95) 2(-2.9,1.3) 3(-2.9,0.65) 4(-2.9,0) 5(-2.9,-0.65) 6(-2.9,-1.3) 7(-2.9,-1.95) 8(2.9,-1.95) 9(2.9,-1.3) 10(2.9,-0.65) 11(2.9,0) 12(2.9,0.65) 13(2.9,1.3) 14(2.9,1.95)
  rect 3.06x3.4 smd: 15(0,0)
  silkscreen extent -2.92,-2.55 1.87,2.79, body extent -3.2,-2.55 3.2,2.55, height 1.2

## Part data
Ccp Cfly Cout: "10uF; 10V; X7R; 10%; 0805; GCM21BR71A106KE22K; Murata", Manufacturer=Murata, Package=0805, Rating=10V, Supplier Part Number 1=490-14531-1-ND, Tolerance=10%, Value/Rating=10u/10V
Cin: "10uF; 10V; X7R; 10%; 0805; GCM21BR71A106KE22K; Murata", Manufacturer=Murata, Package=0805, Rating=10V, Supplier Part Number 1=490-14531-1-ND, Tolerance=10%, Value/Rating=1u/10V
Rro: library part 100k_0402_1%, "100k; 1/16W; 1%; 0402; Yageo", Manufacturer=Yageo, Package=0402, Rating=1/16W, Supplier Part Number 1=311-100KLRCT-ND, Tolerance=1%, Value/Rating=10k/1/16W
U1: "600 mA Buck/ 300 mA Noost Charge Pump Regulator for Automotive"

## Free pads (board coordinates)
  rect 50x80 hole 64 copper offset 25,0: 1(0,900) 2(0,800) 3(0,700) 4(0,600) 5(0,500) 6(0,400) 7(0,298.66) 8(0,200) 9(0,100)
  rect 80x50 hole 64 copper offset 0,25: 10(100,0) 11(200,0) 12(300,0) 13(400,0) 14(500,0) 15(600,0) 16(700,0) 17(800,0) 18(900,0)
  rect 50x80 hole 64 copper offset -25,0: 19(1000,100) 20(1000,200) 21(1000,300) 22(1000,400) 23(1000,500) 24(1000,600) 25(1000,700) 26(1000,800) 27(1000,900)
  rect 80x50 hole 64 copper offset 0,-25: 28(900,1000) 29(800,1000) 30(700,1000) 31(600,1000) 32(500,1000) 33(400,1000) 34(300,1000) 35(200,1000) 36(100,1000)

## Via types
v1: diameter 20, hole 10, Top Layer to Bottom Layer, tented both sides, 244 vias

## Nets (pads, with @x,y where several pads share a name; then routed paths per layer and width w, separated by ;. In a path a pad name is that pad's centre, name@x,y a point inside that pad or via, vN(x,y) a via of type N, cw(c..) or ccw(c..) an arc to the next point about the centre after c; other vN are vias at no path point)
CN: Cfly.2 U1.5
CP: Cfly.1 U1.3
EN: pad.36 U1.10 | length 863.7
  Top Layer w8: v1@474.41,350.59 U1.10
  Bottom Layer w8: pad.36 100,928.88 120,908.88 120,901.72 151.72,870 158.28,870 170,858.28 170,851.72 201.72,820 208.28,820 220,808.28 220,801.72 251.72,770 258.28,770 270,758.28 270,751.72 301.72,720 308.28,720 325,703.28 325,696.72 341.72,680 348.28,680 380,648.28 380,641.72 391.72,630 398.28,630 427.5,600.78 427.5,452.5 475,405 v1(475,350)
GND: Ccp.2 Cin.2 Cout.2 pad.12 pad.13 pad.14 pad.15 pad.16 pad.30 pad.31 pad.32 pad.33 pad.34 U1.8 U1.15
  other v1: 250,100 300,100 350,100 400,100 450,100 500,100 550,100 600,100 650,100 700,100 750,100 250,150 300,150 350,150 400,150 450,150 500,150 550,150 600,150 650,150 700,150 750,150 250,200 300,200 350,200 400,200 450,200 500,200 550,200 599.69,200 650,200 700,200 750,200 300,250 350,250 400,250 450,250 500,250 550,250 600,250 649.69,250 700,250 300,300 350,300 400,300 450,300 500,300 550,300 600,300 650,300 300,350 350,350 400,350 300,400 350,400 400,400 300,450 350,450 400,450 455,455 500,455 545,455 300,500 350,500 400,500 455,500 500,500 545,500 600,500 650,500 455,545 500,545 545,545 300,550 450,750 500,750 550,750 600,750 650,750 400,800 450,800 550,800 600,800 650,800 500,800.91 700,850 300,900 350,900 400,900 450,900 500,900 550,900 600,900 650,900 700,900
RO: pad.28 Rro.2 U1.13 | length 1114.7
  Top Layer w8: v1@551.18,351.18 U1.13 ; Rro.2 860,900 899,939 pad.28@899,999
  Bottom Layer w8: v1(550,350) 550,400 575,425 575,753.28 596.72,775 753.28,775 775,796.72 775,903.28 798.32,926.6 886.6,926.6 900,940 pad.28
VCP: Ccp.1 U1.1
Vin: Cin.1 pad.1 pad.2 pad.3 pad.4 pad.5 pad.6 pad.7 pad.8 pad.9 U1.7
  other v1: 100,100 100,150 150,150 100,200 150,200 200,200 100,250 150,250 200,250 250,250 100,300 150,300 200,300 250,300 100,350 150,350 200,350 250,350 100,400 150,400 200,400 250,400 100,450 150,450 200,450 250,450 100,500 150,500 200,500 250,500 100,550 150,550 200,550 250,550 100,600 150,600 199.84,600 250,600 300,600 100,650 150,650 199.84,650 250,650 300,650 350,650 400,650 100,700 150,700 200,700 250,700 300,700 350,700 400,700 100,750 150,750 200,750 250,750 300,750 350,750 400,750 100,800 150,800 200,800 250,800 300,800 350,800 100,850 150,850 200,850 250,850.4 300.32,849.6 150,900 200,900 250,900 100,900.6
Vout: Cout.1 pad.19 pad.20 pad.21 pad.22 pad.23 pad.24 pad.25 pad.26 pad.27 Rro.1 U1.14
  other v1: 900,100 850,150 900,150 800,200 850,200 900,200 750,250 800,250 850,250 900,250 700,300 750,300 800,300 850,300 900,300 600,350 650,350 700,350 750,350 800,350 850,350 900,350 700,400 750,400 800,400 850,400 900,400 700,450 750,450 800,450 850,450 900,450 700,500 750,500 800,500 850,500 900,500 700,550 750,550 800,550 850,550 900,550 700,600 750,600 800,600 850,600 900,600 700,650 750,650 800,650 850,650 900,650 700,700 750,700 800,700 850,700 900,700 700,750 750,750 800,750 850,750 900,750 700,800 750,800 800,800 850,800 900,800 750,850 800,850 850,850 900,850 900,900
pads on no net: U1.2 U1.4 U1.6 U1.9 U1.11 U1.12

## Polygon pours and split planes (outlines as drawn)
CP on Top Layer "CP_L01_P053" (solid, remove dead copper, pour order 53): 517,594 517,733 565,733 565,660 555,650 540,650 534,644 534,594
CN on Top Layer "CN_L01_P051" (solid, remove dead copper, pour order 51): 483,594 483,733 435,733 435,660 445,650 460,650 466,644 466,594
VCP on Top Layer "VCP_L01_P055" (solid, remove dead copper, pour order 55): 570,590 680,590 680,675 595,675 570,650
GND on Top Layer "GND_L01_P069" (solid, remove dead copper, pour order 69): 260,0 260,50 240,70 240,867.2 260,885 260,910.6 260,1000 740,1000 740,235 760,215 760,70 740,50 740,0
Vin on Top Layer "VIN_L01_P067" (solid, remove dead copper, pour order 67): 0,940 225,940 410,755 410,665 430,645 430,590 405,565 290,565 275,550 275,260 75,60 0,60
Vout on Top Layer "VOUT_L01_P065" (solid, remove dead copper, pour order 65): 690,457.5 690,825 760,895 875,895 920,940 1000,940 1000,60 915,60 635,340 570,340 570,425 666.36,425
Vout on PWR_int "VOUT_L03_P061" (solid, remove dead copper, pour order 61): 1000,940 565,940 565,60 1000,60
Vin on PWR_int "VIN_L03_P059" (solid, remove dead copper, pour order 59): 0,940 435,940 435,60 0,60
GND on Bottom Layer "GND_L04_P063" (solid, remove dead copper, pour order 63): 0.66,998.78 0.66,0 998.78,0 1000,-1.22 1000.66,-0.57 1000.66,998.78
GND on GND_int "GND_L02_P071" (solid, remove dead copper, pour order 71): 0.66,999 0,998.34 0,0 998.78,0 1000,-1.22 1000,998.78

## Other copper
Bottom Layer:
  text "BA0344OA" at 670,825 h40

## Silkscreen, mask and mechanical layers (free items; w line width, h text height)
Top Overlay:
  drawing of 1158 lines, arcs and shapes, not listed
  text "GND" at 370,855.84 h40
  text "NCV48920" at 335,784.18 h40
  text "EN" at 150,755 h40 r90
  text "RO" at 945,735 h40 r90
  text "Vout" at 960,403.44 h40 r90
  text "Vin" at 142.5,397.93 h40 r90
  text "RoHS Compliant" at 406.24,165.07 h20
  text "GND" at 415.07,45 h40
Mechanical 1:
  lines w10: 0,0 0,1000 1000,1000 1000,0 0,0 ; 1000,200 1000,200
